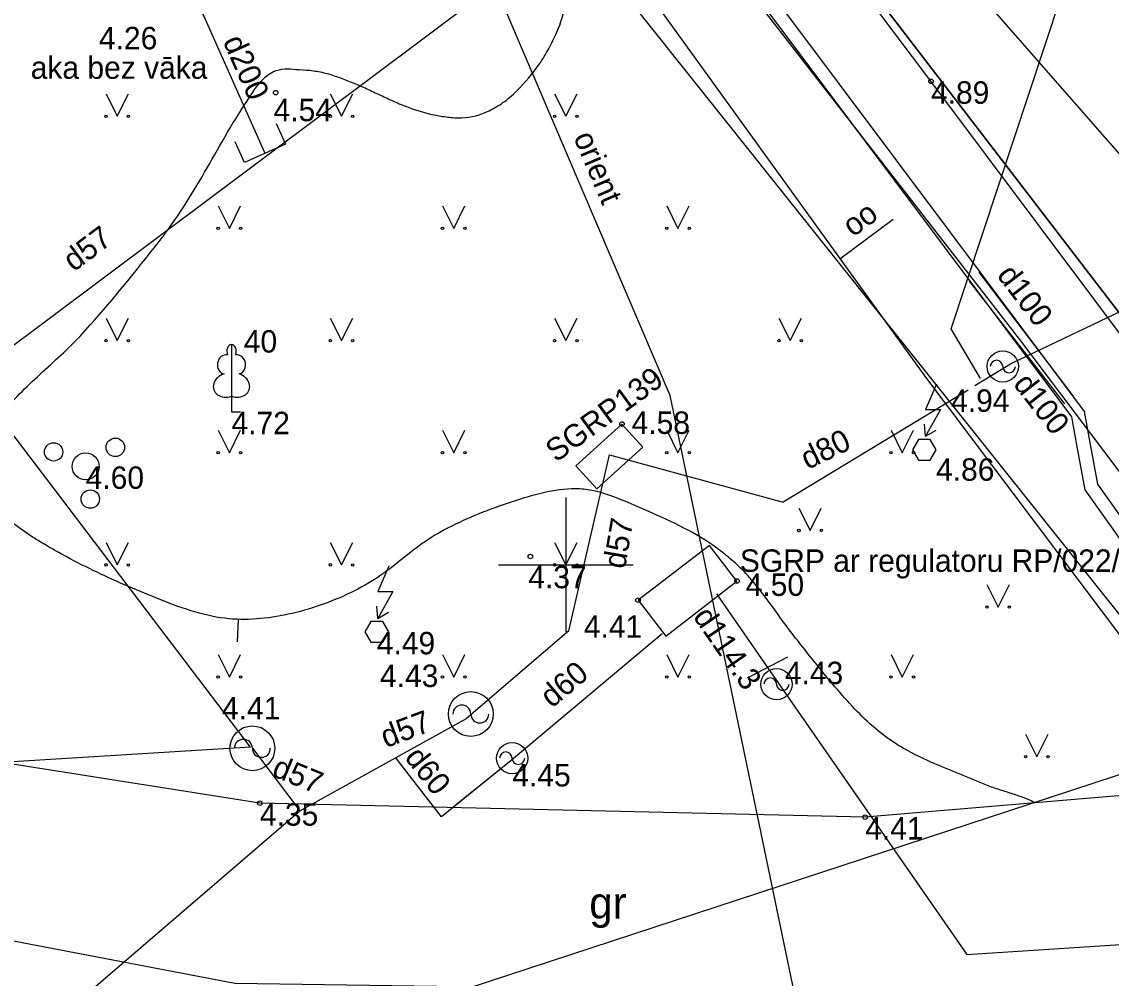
# Model space of a CAD drawing. Extents: x 519536 to 519949, y 326041 to 326519.
# Drawn here: x 519837.87 to 519862.16, y 326190.79 to 326212.11 of the extents above; entities that cross this region are included whole.
import ezdxf

# ---------------------------------------------------------------- set-up
doc = ezdxf.new("R2010")
doc.units = 0
for name, color, linetype in [('APGR_SARK_####_####_#', 7, 'Continuous'), ('CELI_CMAL_####_####_#', 7, 'Continuous'), ('CELI_CSEG_####_TKST_#', 7, 'Continuous'), ('CKOM_ELEM_####_####_#', 7, 'Continuous'), ('CKOM_ELEM_####_TKST_#', 7, 'Continuous'), ('ELEK_ACRL_####_####_#', 7, 'Continuous'), ('ELEK_ACRL_####_TKST_#', 7, 'Continuous'), ('ELEK_VADP_ZSPR_####_#', 7, 'Continuous'), ('GAZE_ELEM_####_####_#', 7, 'Continuous'), ('GAZE_ELEM_####_TKST_#', 7, 'Continuous'), ('GAZE_SKAP_####_####_#', 7, 'Continuous'), ('GAZE_VADP_ASP1_####_#', 7, 'Continuous'), ('GAZE_VADP_ASP1_TKST_#', 7, 'Continuous'), ('GAZE_VADP_NEDR_####_#', 7, 'Continuous'), ('GAZE_VADP_VSP2_####_#', 7, 'Continuous'), ('GAZE_VADP_VSP2_TKST_#', 7, 'Continuous'), ('GAZE_VADP_ZSPD_####_#', 7, 'Continuous'), ('GAZE_VADP_ZSPD_TKST_#', 7, 'Continuous'), ('GEOD_ELEM_####_####_#', 7, 'Continuous'), ('RELJ_AATZ_####_TKST_#', 7, 'Continuous'), ('RELJ_ELEM_####_####_#', 7, 'Continuous'), ('RELJ_HORZ_PAMT_####_#', 7, 'Continuous'), ('ROBZ_PROJ_####_####_#', 7, 'Continuous'), ('ROBZ_UZMR_####_####_#', 7, 'Continuous'), ('SAKK_IZVK_####_TKST_#', 7, 'Continuous'), ('SAKK_KKAN_####_####_#', 7, 'Continuous'), ('SAKT_VADP_NEDR_####_#', 7, 'Continuous'), ('SAKT_VADP_NEDR_TKST_#', 7, 'Continuous'), ('SKAN_ELEM_####_####_#', 7, 'Continuous'), ('SKAN_VADP_NEDR_####_#', 7, 'Continuous'), ('SKAN_VADP_NEDR_TKST_#', 7, 'Continuous'), ('SKAN_VADP_SPDK_####_#', 7, 'Continuous'), ('TERT_DIAM_####_TKST_#', 7, 'Continuous'), ('TERT_ELEM_####_####_#', 7, 'Continuous')]:
    doc.layers.add(name, color=color, linetype=linetype)

msp = doc.modelspace()

# ---------------------------------------------------------------- linework, layer by layer
at = {"layer": 'APGR_SARK_####_####_#'}
msp.add_line((519839.505, 326235.263), (519877.92, 326191.345), dxfattribs=at)
at = {"layer": 'CELI_CMAL_####_####_#'}
for points in [[(519882.222, 326178.789), (519878.977, 326182.88), (519874.995, 326188.433), (519867.888, 326197.765), (519858.139, 326210.779), (519849.58, 326222.15), (519841.494, 326233.418), (519836.895, 326239.916), (519835.264, 326243.212)], [(519838.727, 326233.045), (519841.98, 326228.819), (519851.464, 326216.164), (519860.114, 326205.022), (519866.094, 326197.096), (519865.662, 326195.137), (519856.673, 326194.377), (519843.18, 326194.686), (519834.641, 326196.032), (519819.445, 326200.281), (519805.615, 326205.435), (519803.787, 326207.741), (519804.171, 326210.385)], [(519787.061, 326208.66), (519797.129, 326204.029), (519817.623, 326196.632), (519829.055, 326193.272), (519842.621, 326190.678), (519855.118, 326190.491), (519864.636, 326190.648), (519870.995, 326190.162)]]:
    msp.add_lwpolyline(points, dxfattribs=at)
at = {"layer": 'CKOM_ELEM_####_####_#'}
for p, q in [((519858.014, 326202.866), (519858.255, 326203.005)), ((519845.809, 326198.806), (519846.05, 326198.945))]:
    msp.add_line(p, q, dxfattribs=at)
for points in [[(519858.263, 326204.028), (519858.014, 326203.465), (519858.35, 326203.465), (519858.014, 326202.866), (519857.992, 326203.136)], [(519846.058, 326199.968), (519845.809, 326199.405), (519846.145, 326199.405), (519845.809, 326198.806), (519845.787, 326199.076)]]:
    msp.add_lwpolyline(points, dxfattribs=at)
for points in [[(519857.858, 326202.336), (519858.124, 326202.336), (519858.257, 326202.566), (519858.124, 326202.797), (519857.858, 326202.797), (519857.725, 326202.566)], [(519845.653, 326198.276), (519845.919, 326198.276), (519846.052, 326198.506), (519845.919, 326198.737), (519845.653, 326198.737), (519845.52, 326198.506)]]:
    msp.add_lwpolyline(points, close=True, dxfattribs=at)
at = {"layer": 'ELEK_ACRL_####_####_#'}
for p, q in [((519861.307, 326203.769), (519859.212, 326206.523)), ((519858.992, 326206.324), (519861.118, 326203.591))]:
    msp.add_line(p, q, dxfattribs=at)
at = {"layer": 'ELEK_VADP_ZSPR_####_#'}
for points in [[(519858.585, 326207.398), (519839.95, 326232.294), (519837.409, 326236.472), (519836.785, 326238.116)], [(519858.442, 326207.088), (519839.697, 326232.115), (519837.156, 326236.293), (519836.532, 326237.937)], [(519864.724, 326195.91), (519864.697, 326195.944), (519842.423, 326223.872)], [(519861.698, 326202.68), (519861.564, 326203.421), (519858.585, 326207.398)], [(519861.394, 326202.679), (519861.282, 326203.297), (519858.442, 326207.088)], [(519865.422, 326196.266), (519861.575, 326201.676), (519861.394, 326202.679)], [(519865.693, 326196.404), (519861.859, 326201.796), (519861.698, 326202.68)]]:
    msp.add_lwpolyline(points, dxfattribs=at)
at = {"layer": 'GAZE_ELEM_####_####_#'}
msp.add_line((519854.942, 326197.94), (519854.054, 326197.482), dxfattribs=at)
for centre, radius in [((519859.74, 326204.422), 0.35), ((519854.696, 326197.34), 0.35), ((519847.882, 326196.675), 0.5), ((519843.012, 326195.91), 0.5), ((519848.803, 326195.69), 0.35)]:
    msp.add_circle(centre, radius, dxfattribs=at)
for centre, radius, start, end in [((519859.6, 326204.422), 0.14, 0, 180), ((519859.88, 326204.422), 0.14, 180, 0), ((519854.556, 326197.34), 0.14, 0, 180), ((519854.836, 326197.34), 0.14, 180, 0), ((519847.682, 326196.675), 0.2, 0, 180), ((519848.082, 326196.675), 0.2, 180, 0), ((519842.812, 326195.91), 0.2, 0, 180), ((519843.212, 326195.91), 0.2, 180, 0), ((519848.663, 326195.69), 0.14, 0, 180), ((519848.943, 326195.69), 0.14, 180, 0)]:
    msp.add_arc(centre, radius, start, end, dxfattribs=at)
at = {"layer": 'GAZE_SKAP_####_####_#'}
for points in [[(519851.251, 326203.139), (519850.224, 326202.211), (519850.693, 326201.692), (519851.72, 326202.62), (519851.251, 326203.139)], [(519853.203, 326200.431), (519851.61, 326199.213), (519852.226, 326198.414), (519853.814, 326199.639), (519853.203, 326200.431)]]:
    msp.add_lwpolyline(points, dxfattribs=at)
at = {"layer": 'GAZE_VADP_ASP1_####_#'}
for p, q in [((519853.45, 326216.69), (519836.718, 326204.164)), ((519842.969, 326195.935), (519836.718, 326204.164)), ((519850.065, 326198.526), (519850.972, 326202.454)), ((519850.065, 326198.526), (519847.788, 326196.573)), ((519843.012, 326195.91), (519844.074, 326194.519)), ((519847.227, 326194.386), (519846.209, 326195.7)), ((519848.784, 326195.641), (519847.227, 326194.386))]:
    msp.add_line(p, q, dxfattribs=at)
for points in [[(519852.149, 326198.466), (519848.784, 326195.641)], [(519835.655, 326187.288), (519844.074, 326194.519), (519847.788, 326196.573)], [(519848.784, 326195.641), (519847.528, 326194.629)]]:
    msp.add_lwpolyline(points, dxfattribs=at)
at = {"layer": 'GAZE_VADP_NEDR_####_#'}
msp.add_lwpolyline([(519842.969, 326195.935), (519836.696, 326195.552)], dxfattribs=at)
at = {"layer": 'GAZE_VADP_VSP2_####_#'}
for p, q in [((519853.359, 326199.354), (519854.498, 326197.711)), ((519858.936, 326191.316), (519873.273, 326192.249))]:
    msp.add_line(p, q, dxfattribs=at)
msp.add_lwpolyline([(519854.498, 326197.711), (519858.936, 326191.316)], dxfattribs=at)
at = {"layer": 'GAZE_VADP_ZSPD_####_#'}
for p, q in [((519858.591, 326205.262), (519863.433, 326219.904)), ((519870.805, 326209.689), (519859.952, 326204.495)), ((519859.244, 326204.156), (519858.591, 326205.262)), ((519859.952, 326204.495), (519859.117, 326203.988)), ((519858.966, 326203.897), (519854.848, 326201.398)), ((519850.972, 326202.454), (519854.848, 326201.398))]:
    msp.add_line(p, q, dxfattribs=at)
at = {"layer": 'GEOD_ELEM_####_####_#'}
for p, q in [((519850, 326201.5), (519850, 326200)), ((519848.5, 326200), (519850, 326200)), ((519850, 326200), (519850, 326198.5)), ((519850, 326200), (519851.5, 326200))]:
    msp.add_line(p, q, dxfattribs=at)
at = {"layer": 'RELJ_ELEM_####_####_#'}
for centre in [(519858.139, 326210.779), (519843.532, 326210.526), (519851.251, 326203.139), (519849.209, 326200.185), (519853.814, 326199.639), (519851.61, 326199.213), (519843.18, 326194.686), (519856.673, 326194.377)]:
    msp.add_circle(centre, 0.05, dxfattribs=at)
at = {"layer": 'RELJ_HORZ_PAMT_####_#'}
msp.add_line((519842.695, 326198.782), (519842.674, 326198.282), dxfattribs=at)
for points in [[(519840.915, 326207.181), (519841.085, 326207.409), (519841.598, 326208.164), (519842.062, 326208.95), (519842.52, 326209.745), (519843.015, 326210.524), (519843.213, 326210.79), (519843.336, 326210.904), (519843.485, 326210.996), (519843.736, 326211.055), (519843.988, 326211.045), (519844.295, 326211.024), (519844.602, 326210.971), (519845.217, 326210.762), (519845.525, 326210.631), (519845.827, 326210.49), (519846.131, 326210.349), (519846.447, 326210.215), (519847.06, 326210.031), (519847.369, 326209.981), (519847.676, 326209.964), (519848.291, 326210.123), (519848.599, 326210.304), (519848.752, 326210.424), (519848.906, 326210.565), (519849.412, 326211.167), (519849.619, 326211.504), (519849.799, 326211.872), (519849.999, 326212.524), (519850.035, 326213.183), (519849.751, 326215.81), (519849.692, 326216.196), (519849.509, 326216.777), (519849.31, 326217.343), (519848.844, 326218.429), (519848.247, 326219.452), (519847.89, 326219.953), (519847.692, 326220.187), (519847.475, 326220.412), (519847.2, 326220.634), (519846.893, 326220.808), (519846.26, 326221.054), (519845.594, 326221.222), (519844.941, 326221.422), (519844.349, 326221.765), (519843.967, 326222.11), (519843.619, 326222.477), (519843.025, 326223.288), (519842.037, 326225.053), (519841.137, 326226.889), (519840.439, 326228.789), (519840.324, 326229.35), (519840.258, 326229.919), (519840.197, 326230.49), (519840.099, 326231.054), (519840.034, 326231.347)], [(519837.541, 326203.5), (519837.605, 326203.576), (519838.049, 326204.033), (519838.511, 326204.462), (519838.969, 326204.891), (519839.398, 326205.347), (519840.915, 326207.181)], [(519860.45, 326194.696), (519860.445, 326194.699), (519860.154, 326194.826), (519859.858, 326194.926), (519859.562, 326195.021), (519859.271, 326195.131), (519858.696, 326195.371), (519858.12, 326195.612), (519857.562, 326195.89), (519857.294, 326196.053), (519857.037, 326196.239), (519856.106, 326197.159), (519855.282, 326198.166), (519854.963, 326198.575), (519854.658, 326198.995), (519854.347, 326199.411), (519854.01, 326199.81), (519853.699, 326200.107), (519853.363, 326200.374), (519852.632, 326200.821), (519851.847, 326201.191), (519851.025, 326201.531), (519850.669, 326201.642), (519850.489, 326201.675), (519850.309, 326201.691), (519849.592, 326201.625), (519848.875, 326201.428), (519848.151, 326201.172), (519847.456, 326200.864), (519846.868, 326200.521), (519846.338, 326200.119), (519845.806, 326199.72), (519845.212, 326199.384), (519843.811, 326198.898), (519843.103, 326198.794), (519842.402, 326198.808), (519841.638, 326198.978), (519840.879, 326199.256), (519840.159, 326199.556), (519839.465, 326199.875), (519838.78, 326200.229), (519838.444, 326200.42), (519838.112, 326200.619), (519837.548, 326201.059), (519837.313, 326201.33), (519837.109, 326201.65), (519837.028, 326201.882), (519837.009, 326202.116), (519837.087, 326202.634), (519837.178, 326202.868), (519837.281, 326203.091), (519837.541, 326203.5)]]:
    msp.add_spline(points, degree=3, dxfattribs=at)
at = {"layer": 'ROBZ_PROJ_####_####_#'}
msp.add_line((519876.321, 326187.374), (519841.088, 326233.318), dxfattribs=at)
at = {"layer": 'ROBZ_UZMR_####_####_#'}
msp.add_line((519841.088, 326233.318), (519876.321, 326187.374), dxfattribs=at)
at = {"layer": 'SAKK_IZVK_####_TKST_#'}
msp.add_line((519856.111, 326206.824), (519857.299, 326207.703), dxfattribs=at)
at = {"layer": 'SAKK_KKAN_####_####_#'}
msp.add_lwpolyline([(519835.52, 326236.905), (519836.738, 326233.953), (519845.772, 326221.145), (519858.019, 326204.182), (519864.377, 326195.733)], dxfattribs=at)
at = {"layer": 'SAKT_VADP_NEDR_####_#'}
msp.add_lwpolyline([(519855.446, 326188.769), (519852.328, 326203.775), (519840.835, 326230.671)], dxfattribs=at)
at = {"layer": 'SKAN_ELEM_####_####_#'}
msp.add_lwpolyline([(519843.546, 326209.835), (519843.749, 326209.378), (519842.835, 326208.972), (519842.632, 326209.429)], dxfattribs=at)
at = {"layer": 'SKAN_VADP_NEDR_####_#'}
msp.add_line((519839.867, 326216.88), (519843.292, 326209.175), dxfattribs=at)
at = {"layer": 'SKAN_VADP_SPDK_####_#'}
msp.add_line((519820.834, 326181.72), (519876.847, 326200.081), dxfattribs=at)
at = {"layer": 'TERT_ELEM_####_####_#'}
for p, q in [((519839.75, 326210.5), (519840, 326210)), ((519840, 326210), (519840.25, 326210.5)), ((519844.75, 326210.5), (519845, 326210)), ((519845, 326210), (519845.25, 326210.5)), ((519849.75, 326210.5), (519850, 326210)), ((519850, 326210), (519850.25, 326210.5)), ((519842.25, 326208), (519842.5, 326207.5)), ((519842.5, 326207.5), (519842.75, 326208)), ((519847.25, 326208), (519847.5, 326207.5)), ((519847.5, 326207.5), (519847.75, 326208)), ((519852.25, 326208), (519852.5, 326207.5)), ((519852.5, 326207.5), (519852.75, 326208)), ((519839.75, 326205.5), (519840, 326205)), ((519840, 326205), (519840.25, 326205.5)), ((519844.75, 326205.5), (519845, 326205)), ((519845, 326205), (519845.25, 326205.5)), ((519849.75, 326205.5), (519850, 326205)), ((519850, 326205), (519850.25, 326205.5)), ((519854.75, 326205.5), (519855, 326205)), ((519855, 326205), (519855.25, 326205.5)), ((519842.547, 326203.759), (519842.547, 326203.412)), ((519842.547, 326203.412), (519842.747, 326203.412)), ((519842.25, 326203), (519842.5, 326202.5)), ((519842.5, 326202.5), (519842.75, 326203)), ((519847.25, 326203), (519847.5, 326202.5)), ((519847.5, 326202.5), (519847.75, 326203)), ((519852.25, 326203), (519852.5, 326202.5)), ((519852.5, 326202.5), (519852.75, 326203)), ((519857.25, 326203), (519857.5, 326202.5)), ((519857.5, 326202.5), (519857.75, 326203)), ((519855.194, 326201.267), (519855.444, 326200.767)), ((519855.444, 326200.767), (519855.694, 326201.267)), ((519839.75, 326200.5), (519840, 326200)), ((519840, 326200), (519840.25, 326200.5)), ((519844.75, 326200.5), (519845, 326200)), ((519845, 326200), (519845.25, 326200.5)), ((519849.75, 326200.5), (519850, 326200)), ((519850, 326200), (519850.25, 326200.5)), ((519859.388, 326199.559), (519859.638, 326199.059)), ((519859.638, 326199.059), (519859.888, 326199.559)), ((519842.25, 326198), (519842.5, 326197.5)), ((519842.5, 326197.5), (519842.75, 326198)), ((519847.25, 326198), (519847.5, 326197.5)), ((519847.5, 326197.5), (519847.75, 326198)), ((519852.25, 326198), (519852.5, 326197.5)), ((519852.5, 326197.5), (519852.75, 326198)), ((519857.25, 326198), (519857.5, 326197.5)), ((519857.5, 326197.5), (519857.75, 326198)), ((519860.25, 326196.224), (519860.5, 326195.724)), ((519860.5, 326195.724), (519860.75, 326196.224))]:
    msp.add_line(p, q, dxfattribs=at)
for points in [[(519842.547, 326204.912), (519842.547, 326203.759)], [(519842.637, 326204.68), (519842.636, 326204.681)]]:
    msp.add_lwpolyline(points, dxfattribs=at)
for centre, radius in [((519839.75, 326210), 0.028), ((519840.25, 326210), 0.0263), ((519844.75, 326210), 0.028), ((519845.25, 326210), 0.0263), ((519849.75, 326210), 0.028), ((519850.25, 326210), 0.0263), ((519842.25, 326207.5), 0.028), ((519842.75, 326207.5), 0.0263), ((519847.25, 326207.5), 0.028), ((519847.75, 326207.5), 0.0263), ((519852.25, 326207.5), 0.028), ((519852.75, 326207.5), 0.0263), ((519839.75, 326205), 0.028), ((519840.25, 326205), 0.0263), ((519844.75, 326205), 0.028), ((519845.25, 326205), 0.0263), ((519849.75, 326205), 0.028), ((519850.25, 326205), 0.0263), ((519854.75, 326205), 0.028), ((519855.25, 326205), 0.0263), ((519839.957, 326202.619), 0.207), ((519838.582, 326202.518), 0.204), ((519842.25, 326202.5), 0.028), ((519842.75, 326202.5), 0.0263), ((519847.25, 326202.5), 0.028), ((519847.75, 326202.5), 0.0263), ((519852.25, 326202.5), 0.028), ((519852.75, 326202.5), 0.0263), ((519857.25, 326202.5), 0.028), ((519857.75, 326202.5), 0.0263), ((519839.296, 326202.194), 0.301), ((519839.399, 326201.467), 0.205), ((519855.193, 326200.766), 0.028), ((519855.693, 326200.766), 0.0263), ((519839.75, 326200), 0.028), ((519840.25, 326200), 0.0263), ((519844.75, 326200), 0.028), ((519845.25, 326200), 0.0263), ((519849.75, 326200), 0.028), ((519850.25, 326200), 0.0263), ((519859.388, 326199.059), 0.028), ((519859.888, 326199.059), 0.0263), ((519842.25, 326197.5), 0.028), ((519842.75, 326197.5), 0.0263), ((519847.25, 326197.5), 0.028), ((519847.75, 326197.5), 0.0263), ((519852.25, 326197.5), 0.028), ((519852.75, 326197.5), 0.0263), ((519857.25, 326197.5), 0.028), ((519857.75, 326197.5), 0.0263), ((519860.25, 326195.723), 0.028), ((519860.75, 326195.723), 0.0263)]:
    msp.add_circle(centre, radius, dxfattribs=at)
for centre, major_axis, ratio, start_param, end_param in [((519842.548, 326204.762), (0, -0.15), 0.707107, 3.14537, 5.287485), ((519842.547, 326204.762), (0, -0.15), 0.707107, 0.995701, 3.137816), ((519842.419, 326204.468), (-0.039, -0.212), 0.861323, 3.141593, 6.283185), ((519842.676, 326204.468), (0.039, -0.212), 0.861323, 0, 3.141593), ((519842.458, 326204.005), (0.307, 0.095), 0.814445, 1.570796, 4.752015), ((519842.637, 326204.005), (-0.307, 0.095), 0.814445, 1.531171, 4.712389)]:
    msp.add_ellipse(centre, major_axis=major_axis, ratio=ratio, start_param=start_param, end_param=end_param, dxfattribs=at)

# ---------------------------------------------------------------- texts
at = {"layer": 'CELI_CSEG_####_TKST_#'}
msp.add_text('gr', height=0.7, dxfattribs=at).set_placement((519850.523, 326192.115))
at = {"layer": 'CKOM_ELEM_####_TKST_#'}
for s, p in [('4.26', (519839.592, 326211.492)), ('aka bez vāka', (519838.072, 326210.835))]:
    msp.add_text(s, height=0.5, dxfattribs=at).set_placement(p)
at = {"layer": 'ELEK_ACRL_####_TKST_#'}
for rotation, p in [(307.2607, (519859.591, 326206.453)), (307.8793, (519859.955, 326204.029))]:
    msp.add_text('d100', height=0.5, rotation=rotation, dxfattribs=at).set_placement(p)
at = {"layer": 'GAZE_ELEM_####_TKST_#'}
msp.add_text('SGRP139', height=0.5, rotation=36.0407, dxfattribs=at).set_placement((519849.782, 326202.271))
for s, p in [('4.94', (519858.588, 326203.411)), ('SGRP ar regulatoru RP/022/66', (519853.879, 326199.844)), (' 4.43', (519845.672, 326197.277)), (' 4.43', (519854.696, 326197.34)), ('4.41', (519842.334, 326196.556)), (' 4.45', (519848.621, 326195.06))]:
    msp.add_text(s, height=0.5, dxfattribs=at).set_placement(p)
at = {"layer": 'GAZE_VADP_ASP1_TKST_#'}
for s, rotation, p in [('d57', 36.8186, (519839.031, 326206.521)), (' d57', 80.3846, (519851.288, 326199.711)), ('d60', 40.0143, (519849.689, 326196.793)), (' d57', 20.5543, (519845.814, 326195.848)), ('d60', 308.135, (519846.389, 326195.701)), (' d57', 337.7739, (519843.249, 326195.374))]:
    msp.add_text(s, height=0.5, rotation=rotation, dxfattribs=at).set_placement(p)
at = {"layer": 'GAZE_VADP_VSP2_TKST_#'}
msp.add_text('d114.3', height=0.5, rotation=304.6466, dxfattribs=at).set_placement((519852.821, 326198.846))
at = {"layer": 'GAZE_VADP_ZSPD_TKST_#'}
msp.add_text('d80', height=0.5, rotation=25.711, dxfattribs=at).set_placement((519855.389, 326202.115))
at = {"layer": 'RELJ_AATZ_####_TKST_#'}
for s, p in [('4.89', (519858.139, 326210.279)), ('4.54', (519843.485, 326209.89)), ('4.72', (519842.547, 326202.912)), ('4.58', (519851.466, 326202.919)), ('4.86', (519858.253, 326201.875)), ('4.60', (519839.296, 326201.694)), ('4.37', (519849.163, 326199.479)), ('4.50', (519854.01, 326199.308)), ('4.41', (519850.401, 326198.375)), ('4.49', (519845.786, 326198.006)), ('4.35', (519843.18, 326194.186)), ('4.41', (519856.673, 326193.877))]:
    msp.add_text(s, height=0.5, dxfattribs=at).set_placement(p)
at = {"layer": 'SAKK_IZVK_####_TKST_#'}
msp.add_text('oo', height=0.5, rotation=36.4934, dxfattribs=at).set_placement((519856.402, 326207.293))
at = {"layer": 'SAKT_VADP_NEDR_TKST_#'}
msp.add_text('orient', height=0.5, rotation=293.1374, dxfattribs=at).set_placement((519850.162, 326209.535))
at = {"layer": 'SKAN_VADP_NEDR_TKST_#'}
msp.add_text('d200', height=0.5, rotation=293.9659, dxfattribs=at).set_placement((519842.346, 326211.673))
at = {"layer": 'TERT_DIAM_####_TKST_#'}
msp.add_text('40', height=0.5, dxfattribs=at).set_placement((519842.821, 326204.732))

doc.saveas('drawing.dxf')
